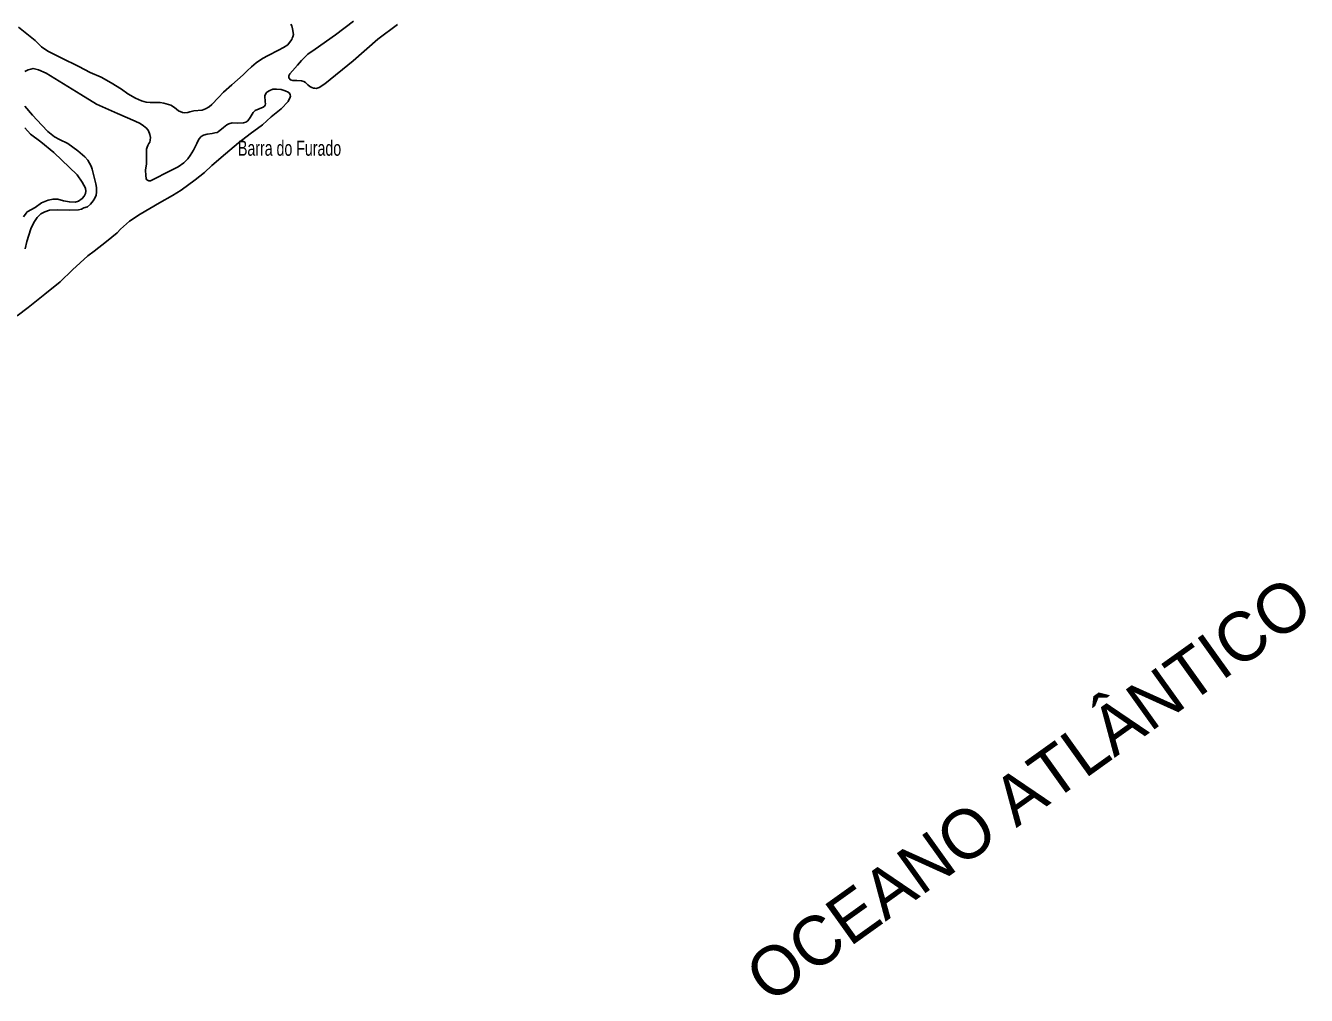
# Model space of a CAD drawing. Extents: x 267.7 to 296, y 7537.7 to 7565.8.
# Drawn here: x 278.74 to 285.51, y 7550.82 to 7555.95 of the extents above; entities that cross this region are included whole.
import ezdxf
from ezdxf.enums import TextEntityAlignment as Align

# ---------------------------------------------------------------- set-up
doc = ezdxf.new("R2010")
doc.units = 0
doc.header["$LTSCALE"] = 0.04
doc.layers.add('1', color=7, linetype='Continuous', lineweight=25)
doc.layers.add('2', color=7, linetype='Continuous', lineweight=25)
doc.layers.add('61', color=7, linetype='Continuous')

msp = doc.modelspace()

# ---------------------------------------------------------------- linework, layer by layer
at = {"layer": '1'}
msp.add_lwpolyline([(278.7051, 7555.9407), (278.7921, 7555.8693)], dxfattribs=at)
at = {"layer": '2'}
for points in [[(280.1436, 7555.9561), (280.1483, 7555.9472), (280.1519, 7555.9324), (280.1578, 7555.901), (280.1548, 7555.8903), (280.1508, 7555.8825), (280.1481, 7555.876), (280.1364, 7555.8589), (280.1272, 7555.848), (280.1042, 7555.8326), (280.0791, 7555.8184), (280.0235, 7555.7912), (279.9934, 7555.7749), (279.96, 7555.7515), (279.9353, 7555.7314), (279.9134, 7555.7101)], [(280.4747, 7555.9725), (280.3792, 7555.8994), (280.2724, 7555.8245), (280.233, 7555.7983), (280.2002, 7555.7645), (280.1787, 7555.7392), (280.1524, 7555.7102), (280.1384, 7555.6933), (280.1337, 7555.683), (280.1337, 7555.6727), (280.1412, 7555.6615), (280.1534, 7555.6587), (280.1759, 7555.6587), (280.1993, 7555.6568), (280.2115, 7555.653), (280.2218, 7555.6474), (280.2339, 7555.6352), (280.2433, 7555.6268), (280.2546, 7555.6212), (280.2639, 7555.6174), (280.2703, 7555.6173)], [(280.2703, 7555.6173), (280.2766, 7555.6171), (280.2936, 7555.6218), (280.324, 7555.6411), (280.4732, 7555.7622), (280.6026, 7555.8775), (280.7073, 7555.9548)], [(278.7921, 7555.8693), (278.8258, 7555.8367), (278.8597, 7555.8138), (278.9308, 7555.7782), (279.0227, 7555.7335), (279.0838, 7555.7005), (279.1406, 7555.6758), (279.1933, 7555.647), (279.2493, 7555.6135), (279.2819, 7555.5876), (279.3225, 7555.565), (279.3542, 7555.5516), (279.3785, 7555.5441), (279.4011, 7555.5416), (279.4228, 7555.5424), (279.4404, 7555.542), (279.4529, 7555.5416), (279.4717, 7555.5387), (279.5093, 7555.5291), (279.5294, 7555.5153), (279.5495, 7555.4985), (279.5716, 7555.4902), (279.5833, 7555.4885), (279.5988, 7555.4894), (279.6105, 7555.4935), (279.6314, 7555.4981), (279.6753, 7555.5019), (279.6924, 7555.5082), (279.7117, 7555.519), (279.7255, 7555.5312), (279.7618, 7555.5696), (279.7878, 7555.5964), (279.8321, 7555.6352), (279.8914, 7555.6888), (279.9134, 7555.7101)], [(278.7372, 7555.7063), (278.7552, 7555.7151), (278.7694, 7555.7189), (278.7817, 7555.7216), (278.8108, 7555.7158), (278.8507, 7555.6966), (279.0338, 7555.5843), (279.117, 7555.5335), (279.2269, 7555.4836), (279.3201, 7555.4445), (279.3474, 7555.4323), (279.3658, 7555.4195), (279.3823, 7555.4054), (279.3908, 7555.3919), (279.3982, 7555.3736), (279.4012, 7555.3583), (279.4006, 7555.343), (279.3982, 7555.3332), (279.3939, 7555.3259), (279.3878, 7555.3149), (279.3841, 7555.3063), (279.3817, 7555.2953), (279.3817, 7555.2176), (279.3762, 7555.1846), (279.3768, 7555.1559), (279.3798, 7555.14), (279.3817, 7555.1351), (279.386, 7555.1314), (279.3939, 7555.1284), (279.4019, 7555.129), (279.43, 7555.143), (279.485, 7555.1712), (279.5474, 7555.2024), (279.578, 7555.2238), (279.6, 7555.2439), (279.6116, 7555.2629), (279.6294, 7555.2904), (279.6465, 7555.3259), (279.6575, 7555.3479), (279.6691, 7555.362), (279.6819, 7555.3705)], [(279.759, 7555.3877), (279.7871, 7555.4109), (279.8049, 7555.425), (279.8159, 7555.4305), (279.8336, 7555.4354), (279.863, 7555.4335), (279.8935, 7555.4354), (279.9058, 7555.4384), (279.9156, 7555.4458), (279.9278, 7555.4623), (279.9437, 7555.4898), (279.9559, 7555.5002), (279.9767, 7555.5094), (279.9969, 7555.5179), (280.0036, 7555.5234), (280.0073, 7555.5277), (280.0097, 7555.5357), (280.0085, 7555.5454), (280.0067, 7555.5772), (280.011, 7555.5895), (280.0171, 7555.5968), (280.0324, 7555.6066), (280.0477, 7555.6121)], [(280.0477, 7555.6121), (280.0685, 7555.6121), (280.0917, 7555.6103), (280.1137, 7555.6042), (280.129, 7555.5974), (280.1363, 7555.5925), (280.1406, 7555.5821), (280.1412, 7555.5754), (280.1406, 7555.5699)], [(280.1406, 7555.5699), (280.1286, 7555.5479), (280.0919, 7555.5085), (280.0391, 7555.4664), (279.9943, 7555.4243), (279.9281, 7555.376), (279.8672, 7555.3285), (279.7983, 7555.2712), (279.7257, 7555.2103), (279.6872, 7555.1732), (279.6384, 7555.1342), (279.5639, 7555.0783), (279.5187, 7555.0508), (279.4504, 7555.0127), (279.3476, 7554.9524), (279.2917, 7554.9151), (279.243, 7554.8726), (279.2261, 7554.8531), (279.1694, 7554.8087), (279.1046, 7554.7564), (279.071, 7554.7316), (278.9903, 7554.658), (278.9247, 7554.5951), (278.844, 7554.5303), (278.7553, 7554.4585), (278.6968, 7554.4151)], [(278.7389, 7554.7686), (278.7477, 7554.8075), (278.7698, 7554.8748), (278.7853, 7554.9083), (278.8024, 7554.9338), (278.8233, 7554.9534), (278.8434, 7554.9651), (278.8681, 7554.9735), (278.9099, 7554.976), (278.9717, 7554.9739), (279.0215, 7554.9752), (279.0374, 7554.9793), (279.0503, 7554.9852), (279.0691, 7554.9919), (279.0846, 7555.0048), (279.0988, 7555.0224), (279.108, 7555.0366), (279.1147, 7555.0529), (279.1168, 7555.0688), (279.1164, 7555.0939), (279.1139, 7555.1127), (279.0946, 7555.1896), (279.0879, 7555.2059), (279.0708, 7555.2373), (279.0549, 7555.2557), (279.0181, 7555.2862), (278.9659, 7555.3255), (278.9207, 7555.3468), (278.894, 7555.3618), (278.8601, 7555.3886), (278.8279, 7555.4225), (278.7778, 7555.476), (278.7385, 7555.5236)], [(278.7311, 7554.9376), (278.7443, 7554.957), (278.7505, 7554.9639), (278.7918, 7554.9877), (278.8269, 7555.0121), (278.8613, 7555.0259), (278.887, 7555.0322), (278.9127, 7555.0322), (278.9415, 7555.0234), (278.9734, 7555.0171), (279.0035, 7555.0153), (279.0216, 7555.0209), (279.0416, 7555.0347), (279.0517, 7555.0472), (279.0579, 7555.061), (279.0604, 7555.0741), (279.0579, 7555.0904), (279.0404, 7555.1211), (279.0141, 7555.1593), (278.892, 7555.2776), (278.8225, 7555.3352), (278.7687, 7555.3753), (278.7374, 7555.4084)], [(279.6819, 7555.3705), (279.7021, 7555.3754), (279.7284, 7555.3791), (279.7419, 7555.3815), (279.7535, 7555.384), (279.759, 7555.3877)]]:
    msp.add_lwpolyline(points, dxfattribs=at)

# ---------------------------------------------------------------- texts
at = {"layer": '61', "width": 0.7}
msp.add_text('Barra do Furado', height=0.08, dxfattribs=at).set_placement((279.8641, 7555.261))
at = {"layer": '61'}
msp.add_text('OCEANO ATLÂNTICO', height=0.26, rotation=35.572, dxfattribs=at).set_placement((284.1179, 7551.8082), align=Align.CENTER)

doc.saveas('drawing.dxf')
